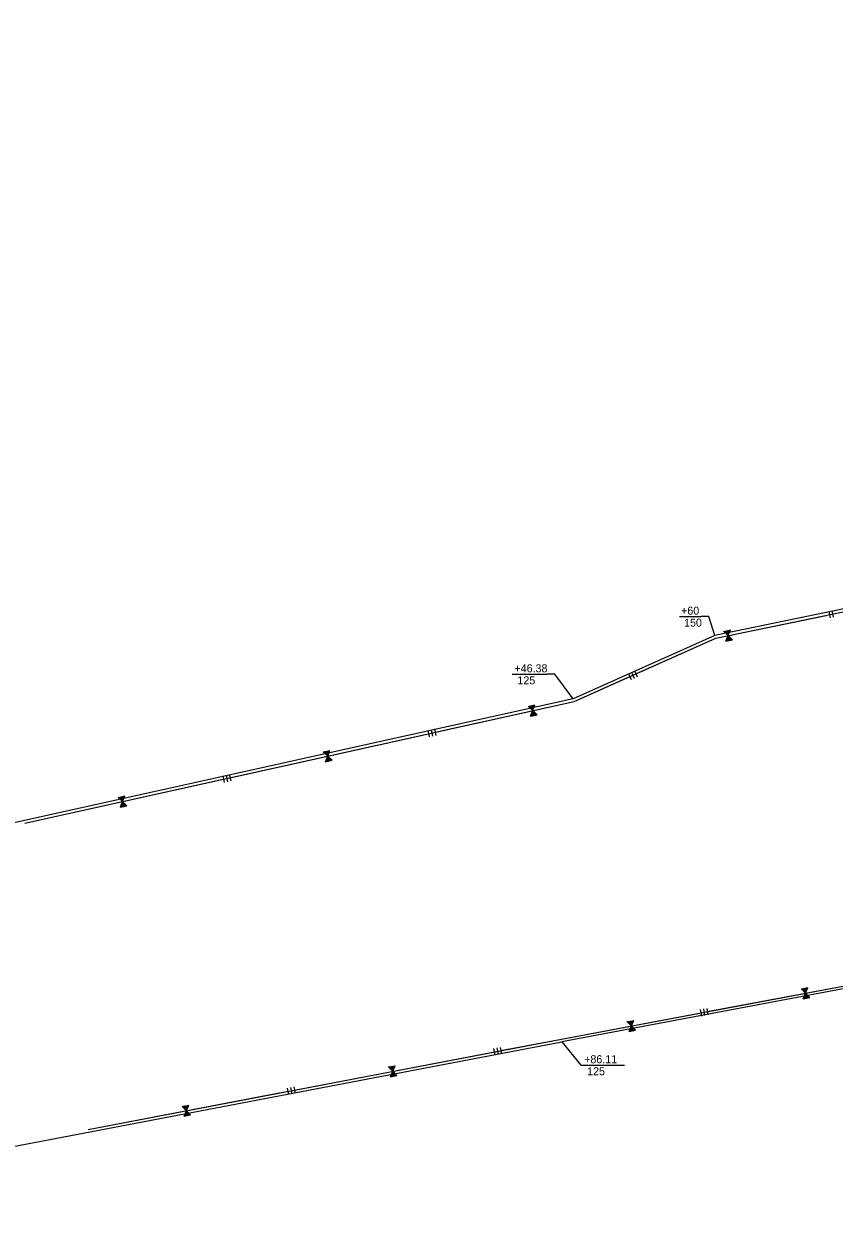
# Model space of a CAD drawing. Extents: x 979729 to 993523, y 1834148 to 1845433.
# Drawn here: x 988823 to 989431, y 1838471 to 1839360 of the extents above; entities that cross this region are included whole.
import ezdxf

# ---------------------------------------------------------------- set-up
doc = ezdxf.new("R2010")
doc.units = 0
for name, color, linetype in [('42', 7, 'Continuous'), ('51', 7, 'Continuous'), ('R_Draft', 7, 'Continuous')]:
    doc.layers.add(name, color=color, linetype=linetype)

msp = doc.modelspace()

# ---------------------------------------------------------------- linework, layer by layer
at = {"layer": '42'}
for p, q in [((989341.75, 1838899.73), (989537.09, 1838940.06)), ((989426.47, 1838919.77), (989427.48, 1838914.88)), ((989428.92, 1838920.28), (989429.93, 1838915.38)), ((989347.87, 1838904.82), (989351.08, 1838901.65)), ((989347.94, 1838904.78), (989347.96, 1838904.84)), ((989348.14, 1838904.61), (989348.26, 1838904.9)), ((989348.32, 1838904.4), (989348.55, 1838904.96)), ((989348.52, 1838904.23), (989348.84, 1838905.02)), ((989348.71, 1838904.02), (989349.14, 1838905.08)), ((989348.89, 1838903.81), (989349.43, 1838905.14)), ((989349.09, 1838903.64), (989349.73, 1838905.21)), ((989349.32, 1838903.53), (989349.96, 1838905.11)), ((989349.49, 1838903.28), (989350.31, 1838905.33)), ((989349.69, 1838903.11), (989350.61, 1838905.39)), ((989349.86, 1838902.88), (989350.9, 1838905.45)), ((989350.08, 1838902.73), (989351.2, 1838905.51)), ((989350.25, 1838902.5), (989351.49, 1838905.57)), ((989350.45, 1838902.33), (989351.79, 1838905.63)), ((989350.63, 1838902.12), (989352.08, 1838905.69)), ((989350.84, 1838901.97), (989352.37, 1838905.75)), ((989351.02, 1838901.74), (989352.67, 1838905.81)), ((989351.08, 1838901.65), (989352.77, 1838905.83)), ((989235.55, 1838852.28), (989341.75, 1838899.73)), ((989349.39, 1838897.48), (989351.08, 1838901.65)), ((989349.43, 1838897.54), (989349.48, 1838897.5)), ((989349.55, 1838897.78), (989349.77, 1838897.56)), ((989349.63, 1838898.04), (989350.07, 1838897.62)), ((989349.75, 1838898.28), (989350.36, 1838897.68)), ((989349.84, 1838898.55), (989350.65, 1838897.74)), ((989349.93, 1838898.81), (989350.95, 1838897.8)), ((989350.04, 1838899.05), (989351.24, 1838897.86)), ((989350.2, 1838899.24), (989351.42, 1838898.04)), ((989350.26, 1838899.53), (989351.83, 1838897.98)), ((989350.38, 1838899.77), (989352.13, 1838898.04)), ((989350.45, 1838900.05), (989352.42, 1838898.1)), ((989350.58, 1838900.27), (989352.71, 1838898.16)), ((989350.65, 1838900.55), (989353.01, 1838898.22)), ((989350.77, 1838900.79), (989353.3, 1838898.29)), ((989350.85, 1838901.05), (989353.6, 1838898.35)), ((989350.99, 1838901.27), (989353.89, 1838898.41)), ((989351.06, 1838901.56), (989354.18, 1838898.47)), ((989351.08, 1838901.65), (989354.28, 1838898.49)), ((989276.38, 1838873.26), (989278.42, 1838868.7)), ((989278.67, 1838874.28), (989280.71, 1838869.72)), ((989280.95, 1838875.3), (989282.99, 1838870.74)), ((988823.9, 1838760.95), (989235.55, 1838852.28)), ((989204.58, 1838845.51), (989206.17, 1838849.6)), ((989204.64, 1838845.42), (989206.27, 1838849.63)), ((989201.39, 1838848.54), (989204.64, 1838845.42)), ((989201.46, 1838848.5), (989201.48, 1838848.56)), ((989201.66, 1838848.33), (989201.77, 1838848.63)), ((989201.85, 1838848.13), (989202.07, 1838848.69)), ((989202.05, 1838847.96), (989202.36, 1838848.76)), ((989202.24, 1838847.75), (989202.65, 1838848.82)), ((989202.43, 1838847.55), (989202.95, 1838848.89)), ((989202.63, 1838847.38), (989203.24, 1838848.95)), ((989202.86, 1838847.27), (989203.47, 1838848.86)), ((989203.01, 1838841.22), (989204.64, 1838845.42)), ((989203.03, 1838847.03), (989203.83, 1838849.08)), ((989203.06, 1838841.29), (989203.1, 1838841.24)), ((989203.17, 1838841.53), (989203.4, 1838841.31)), ((989203.23, 1838846.86), (989204.12, 1838849.15)), ((989203.25, 1838841.79), (989203.69, 1838841.37)), ((989203.37, 1838842.03), (989203.98, 1838841.44)), ((989203.41, 1838846.63), (989204.41, 1838849.21)), ((989203.45, 1838842.3), (989204.28, 1838841.5)), ((989203.53, 1838842.56), (989204.57, 1838841.57)), ((989203.62, 1838846.49), (989204.71, 1838849.28)), ((989203.64, 1838842.8), (989204.86, 1838841.63)), ((989203.8, 1838846.25), (989205, 1838849.34)), ((989203.8, 1838842.99), (989205.04, 1838841.81)), ((989203.86, 1838843.29), (989205.45, 1838841.76)), ((989203.97, 1838843.53), (989205.74, 1838841.83)), ((989204, 1838846.09), (989205.29, 1838849.41)), ((989204.04, 1838843.81), (989206.04, 1838841.89)), ((989204.17, 1838844.03), (989206.33, 1838841.96)), ((989204.19, 1838845.88), (989205.59, 1838849.47)), ((989204.23, 1838844.32), (989206.62, 1838842.02)), ((989204.34, 1838844.55), (989206.92, 1838842.09)), ((989204.41, 1838845.74), (989205.88, 1838849.54)), ((989204.43, 1838844.82), (989207.21, 1838842.15)), ((989204.56, 1838845.04), (989207.5, 1838842.22)), ((989204.62, 1838845.33), (989207.8, 1838842.28)), ((989204.64, 1838845.42), (989207.89, 1838842.3)), ((989126, 1838830.54), (989127.08, 1838825.65)), ((989128.44, 1838831.08), (989129.52, 1838826.2)), ((989130.88, 1838831.62), (989131.96, 1838826.74)), ((989047.63, 1838814.43), (989050.88, 1838811.31)), ((989047.7, 1838814.39), (989047.72, 1838814.45)), ((989047.9, 1838814.22), (989048.01, 1838814.51)), ((989048.09, 1838814.01), (989048.31, 1838814.58)), ((989048.29, 1838813.84), (989048.6, 1838814.64)), ((989048.48, 1838813.64), (989048.89, 1838814.71)), ((989048.67, 1838813.43), (989049.19, 1838814.77)), ((989048.87, 1838813.26), (989049.48, 1838814.84)), ((989049.09, 1838813.16), (989049.71, 1838814.75)), ((989049.27, 1838812.91), (989050.07, 1838814.97)), ((989049.47, 1838812.75), (989050.36, 1838815.03)), ((989049.65, 1838812.51), (989050.65, 1838815.1)), ((989049.86, 1838812.37), (989050.95, 1838815.16)), ((989050.04, 1838812.14), (989051.24, 1838815.23)), ((989050.24, 1838811.97), (989051.53, 1838815.29)), ((989050.43, 1838811.77), (989051.82, 1838815.36)), ((989050.64, 1838811.62), (989052.12, 1838815.42)), ((989050.82, 1838811.39), (989052.41, 1838815.49)), ((989050.88, 1838811.31), (989052.51, 1838815.51)), ((989049.25, 1838807.11), (989050.88, 1838811.31)), ((989049.3, 1838807.17), (989049.34, 1838807.13)), ((989049.41, 1838807.41), (989049.64, 1838807.19)), ((989049.49, 1838807.68), (989049.93, 1838807.26)), ((989049.61, 1838807.91), (989050.22, 1838807.32)), ((989049.69, 1838808.18), (989050.52, 1838807.39)), ((989049.77, 1838808.45), (989050.81, 1838807.45)), ((989049.88, 1838808.69), (989051.1, 1838807.52)), ((989050.04, 1838808.88), (989051.28, 1838807.7)), ((989050.1, 1838809.17), (989051.69, 1838807.65)), ((989050.21, 1838809.41), (989051.98, 1838807.71)), ((989050.28, 1838809.7), (989052.28, 1838807.78)), ((989050.41, 1838809.92), (989052.57, 1838807.84)), ((989050.47, 1838810.2), (989052.86, 1838807.91)), ((989050.58, 1838810.44), (989053.16, 1838807.97)), ((989050.67, 1838810.71), (989053.45, 1838808.04)), ((989050.8, 1838810.92), (989053.74, 1838808.1)), ((989050.86, 1838811.21), (989054.04, 1838808.17)), ((989050.88, 1838811.31), (989054.13, 1838808.19)), ((988972.24, 1838796.42), (988973.32, 1838791.54)), ((988974.68, 1838796.96), (988975.76, 1838792.08)), ((988977.12, 1838797.5), (988978.2, 1838792.62)), ((988893.87, 1838780.31), (988897.12, 1838777.19)), ((988893.93, 1838780.27), (988893.96, 1838780.33)), ((988894.14, 1838780.1), (988894.25, 1838780.4)), ((988894.32, 1838779.9), (988894.54, 1838780.46)), ((988894.53, 1838779.73), (988894.84, 1838780.53)), ((988894.72, 1838779.52), (988895.13, 1838780.59)), ((988894.9, 1838779.32), (988895.42, 1838780.66)), ((988895.11, 1838779.15), (988895.72, 1838780.72)), ((988895.33, 1838779.04), (988895.95, 1838780.63)), ((988895.51, 1838778.8), (988896.3, 1838780.85)), ((988895.71, 1838778.63), (988896.6, 1838780.92)), ((988895.89, 1838778.4), (988896.89, 1838780.98)), ((988896.1, 1838778.26), (988897.19, 1838781.05)), ((988896.28, 1838778.02), (988897.48, 1838781.11)), ((988896.48, 1838777.86), (988897.77, 1838781.18)), ((988896.67, 1838777.65), (988898.06, 1838781.24)), ((988896.88, 1838777.51), (988898.36, 1838781.31)), ((988897.06, 1838777.28), (988898.65, 1838781.37)), ((988897.12, 1838777.19), (988898.75, 1838781.4)), ((988895.49, 1838772.99), (988897.12, 1838777.19)), ((988895.54, 1838773.06), (988895.58, 1838773.01)), ((988895.65, 1838773.3), (988895.88, 1838773.08)), ((988895.73, 1838773.56), (988896.17, 1838773.14)), ((988895.84, 1838773.8), (988896.46, 1838773.21)), ((988895.93, 1838774.07), (988896.76, 1838773.27)), ((988896.01, 1838774.33), (988897.05, 1838773.34)), ((988896.12, 1838774.57), (988897.34, 1838773.4)), ((988896.28, 1838774.76), (988897.52, 1838773.58)), ((988896.34, 1838775.06), (988897.93, 1838773.53)), ((988896.45, 1838775.3), (988898.22, 1838773.6)), ((988896.51, 1838775.58), (988898.52, 1838773.66)), ((988896.65, 1838775.8), (988898.81, 1838773.73)), ((988896.71, 1838776.09), (988899.1, 1838773.79)), ((988896.82, 1838776.32), (988899.4, 1838773.86)), ((988896.91, 1838776.59), (988899.69, 1838773.92)), ((988897.04, 1838776.81), (988899.98, 1838773.99)), ((988897.1, 1838777.1), (988900.28, 1838774.05)), ((988897.12, 1838777.19), (988900.37, 1838774.07)), ((989226.06, 1838599.13), (989775.94, 1838702.44)), ((989406.03, 1838636.76), (989409.18, 1838633.53)), ((989406.09, 1838636.72), (989406.12, 1838636.78)), ((989406.29, 1838636.54), (989406.42, 1838636.83)), ((989406.47, 1838636.33), (989406.71, 1838636.89)), ((989406.67, 1838636.15), (989407.01, 1838636.94)), ((989406.85, 1838635.94), (989407.3, 1838637)), ((989407.03, 1838635.73), (989407.6, 1838637.05)), ((989407.23, 1838635.55), (989407.89, 1838637.11)), ((989407.45, 1838635.44), (989408.12, 1838637.01)), ((989407.62, 1838635.19), (989408.48, 1838637.22)), ((989407.82, 1838635.02), (989408.78, 1838637.27)), ((989407.99, 1838634.78), (989409.07, 1838637.33)), ((989408.2, 1838634.63), (989409.37, 1838637.39)), ((989408.37, 1838634.39), (989409.66, 1838637.44)), ((989408.56, 1838634.22), (989409.96, 1838637.5)), ((989408.74, 1838634.01), (989410.25, 1838637.55)), ((989408.95, 1838633.86), (989410.55, 1838637.61)), ((989409.12, 1838633.62), (989410.84, 1838637.66)), ((989409.18, 1838633.53), (989410.94, 1838637.68)), ((989407.41, 1838629.39), (989409.18, 1838633.53)), ((989407.46, 1838629.45), (989407.5, 1838629.4)), ((989407.58, 1838629.69), (989407.8, 1838629.46)), ((989407.67, 1838629.95), (989408.1, 1838629.52)), ((989407.79, 1838630.18), (989408.39, 1838629.57)), ((989407.88, 1838630.45), (989408.69, 1838629.63)), ((989407.98, 1838630.71), (989408.98, 1838629.68)), ((989408.1, 1838630.95), (989409.28, 1838629.74)), ((989408.26, 1838631.13), (989409.46, 1838629.91)), ((989408.33, 1838631.42), (989409.87, 1838629.85)), ((989408.45, 1838631.66), (989410.16, 1838629.9)), ((989408.52, 1838631.94), (989410.46, 1838629.96)), ((989408.66, 1838632.16), (989410.75, 1838630.01)), ((989408.73, 1838632.44), (989411.05, 1838630.07)), ((989408.85, 1838632.67), (989411.34, 1838630.13)), ((989408.94, 1838632.94), (989411.64, 1838630.18)), ((989409.08, 1838633.15), (989411.93, 1838630.24)), ((989409.16, 1838633.44), (989412.23, 1838630.29)), ((989409.18, 1838633.53), (989412.33, 1838630.31)), ((989330.09, 1838621.22), (989331.02, 1838616.31)), ((989332.55, 1838621.68), (989333.47, 1838616.77)), ((989335.01, 1838622.14), (989335.93, 1838617.23)), ((989275.42, 1838612.16), (989278.57, 1838608.94)), ((989275.48, 1838612.12), (989275.51, 1838612.18)), ((989275.68, 1838611.94), (989275.8, 1838612.23)), ((989275.86, 1838611.73), (989276.1, 1838612.29)), ((989276.06, 1838611.55), (989276.4, 1838612.34)), ((989276.24, 1838611.34), (989276.69, 1838612.4)), ((989276.42, 1838611.13), (989276.99, 1838612.45)), ((989276.62, 1838610.96), (989277.28, 1838612.51)), ((989276.84, 1838610.84), (989277.51, 1838612.41)), ((989277.01, 1838610.59), (989277.87, 1838612.62)), ((989277.21, 1838610.42), (989278.17, 1838612.68)), ((989277.38, 1838610.18), (989278.46, 1838612.73)), ((989277.59, 1838610.03), (989278.76, 1838612.79)), ((989277.76, 1838609.79), (989279.05, 1838612.84)), ((989277.95, 1838609.62), (989279.35, 1838612.9)), ((989278.13, 1838609.41), (989279.64, 1838612.95)), ((989278.34, 1838609.26), (989279.94, 1838613.01)), ((989278.51, 1838609.02), (989280.23, 1838613.06)), ((989278.57, 1838608.94), (989280.33, 1838613.08)), ((989276.8, 1838604.79), (989278.57, 1838608.94)), ((989276.85, 1838604.85), (989276.89, 1838604.81)), ((989276.97, 1838605.09), (989277.19, 1838604.86)), ((989277.06, 1838605.35), (989277.48, 1838604.92)), ((989277.18, 1838605.58), (989277.78, 1838604.97)), ((989277.27, 1838605.85), (989278.07, 1838605.03)), ((989277.37, 1838606.11), (989278.37, 1838605.08)), ((989277.49, 1838606.35), (989278.67, 1838605.14)), ((989277.65, 1838606.53), (989278.84, 1838605.31)), ((989277.72, 1838606.83), (989279.26, 1838605.25)), ((989277.84, 1838607.06), (989279.55, 1838605.3)), ((989277.91, 1838607.34), (989279.85, 1838605.36)), ((989278.05, 1838607.56), (989280.14, 1838605.42)), ((989278.12, 1838607.84), (989280.44, 1838605.47)), ((989278.24, 1838608.08), (989280.73, 1838605.53)), ((989278.33, 1838608.34), (989281.03, 1838605.58)), ((989278.47, 1838608.55), (989281.32, 1838605.64)), ((989278.55, 1838608.84), (989281.62, 1838605.69)), ((989278.57, 1838608.94), (989281.72, 1838605.71)), ((988871.3, 1838531.37), (989226.06, 1838599.13)), ((989175.32, 1838591.98), (989176.26, 1838587.07)), ((989177.78, 1838592.45), (989178.72, 1838587.54)), ((989180.23, 1838592.92), (989181.17, 1838588.01)), ((989096.51, 1838578.2), (989099.67, 1838574.99)), ((989096.57, 1838578.16), (989096.6, 1838578.22)), ((989096.77, 1838577.99), (989096.89, 1838578.28)), ((989096.95, 1838577.77), (989097.19, 1838578.33)), ((989097.15, 1838577.6), (989097.48, 1838578.39)), ((989097.33, 1838577.39), (989097.78, 1838578.45)), ((989097.52, 1838577.18), (989098.08, 1838578.5)), ((989097.71, 1838577), (989098.37, 1838578.56)), ((989097.91, 1838570.84), (989099.67, 1838574.99)), ((989097.94, 1838576.89), (989098.6, 1838578.46)), ((989098.1, 1838576.64), (989098.96, 1838578.67)), ((989098.3, 1838576.47), (989099.26, 1838578.73)), ((989098.47, 1838576.23), (989099.55, 1838578.78)), ((989098.68, 1838576.08), (989099.85, 1838578.84)), ((989098.85, 1838575.84), (989100.14, 1838578.9)), ((989099.05, 1838575.67), (989100.44, 1838578.95)), ((989099.23, 1838575.46), (989100.73, 1838579.01)), ((989099.23, 1838573.89), (989101.55, 1838571.53)), ((989099.34, 1838574.13), (989101.84, 1838571.59)), ((989099.44, 1838575.31), (989101.03, 1838579.07)), ((989099.44, 1838574.39), (989102.14, 1838571.64)), ((989099.57, 1838574.61), (989102.43, 1838571.7)), ((989099.61, 1838575.07), (989101.32, 1838579.12)), ((989099.65, 1838574.89), (989102.73, 1838571.76)), ((989099.67, 1838574.99), (989101.42, 1838579.14)), ((989099.67, 1838574.99), (989102.83, 1838571.77)), ((989097.96, 1838570.9), (989098.01, 1838570.85)), ((989098.08, 1838571.14), (989098.3, 1838570.91)), ((989098.17, 1838571.4), (989098.6, 1838570.97)), ((989098.29, 1838571.63), (989098.89, 1838571.02)), ((989098.38, 1838571.9), (989099.19, 1838571.08)), ((989098.47, 1838572.16), (989099.48, 1838571.14)), ((989098.59, 1838572.4), (989099.78, 1838571.19)), ((989098.76, 1838572.59), (989099.96, 1838571.37)), ((989098.82, 1838572.88), (989100.37, 1838571.3)), ((989098.94, 1838573.11), (989100.66, 1838571.36)), ((989099.01, 1838573.39), (989100.96, 1838571.42)), ((989099.15, 1838573.61), (989101.25, 1838571.47)), ((989020.62, 1838562.43), (989021.56, 1838557.52)), ((989023.07, 1838562.9), (989024.01, 1838557.99)), ((989025.53, 1838563.37), (989026.47, 1838558.46)), ((988941.8, 1838548.65), (988944.96, 1838545.44)), ((988941.87, 1838548.61), (988941.9, 1838548.67)), ((988942.07, 1838548.44), (988942.19, 1838548.73)), ((988942.25, 1838548.22), (988942.49, 1838548.78)), ((988942.45, 1838548.05), (988942.78, 1838548.84)), ((988942.63, 1838547.84), (988943.08, 1838548.9)), ((988942.81, 1838547.63), (988943.37, 1838548.95)), ((988943.01, 1838547.45), (988943.67, 1838549.01)), ((988943.23, 1838547.34), (988943.9, 1838548.91)), ((988943.4, 1838547.09), (988944.26, 1838549.12)), ((988943.6, 1838546.92), (988944.55, 1838549.18)), ((988943.77, 1838546.68), (988944.85, 1838549.23)), ((988943.98, 1838546.53), (988945.14, 1838549.29)), ((988944.15, 1838546.29), (988945.44, 1838549.35)), ((988944.35, 1838546.12), (988945.73, 1838549.4)), ((988944.53, 1838545.91), (988946.03, 1838549.46)), ((988944.74, 1838545.76), (988946.32, 1838549.52)), ((988944.91, 1838545.52), (988946.62, 1838549.57)), ((988944.96, 1838545.44), (988946.72, 1838549.59)), ((988943.21, 1838541.29), (988944.96, 1838545.44)), ((988943.26, 1838541.35), (988943.3, 1838541.3)), ((988943.38, 1838541.59), (988943.6, 1838541.36)), ((988943.47, 1838541.85), (988943.89, 1838541.42)), ((988943.59, 1838542.08), (988944.19, 1838541.47)), ((988943.68, 1838542.35), (988944.48, 1838541.53)), ((988943.77, 1838542.61), (988944.78, 1838541.59)), ((988943.89, 1838542.85), (988945.07, 1838541.64)), ((988944.05, 1838543.04), (988945.25, 1838541.82)), ((988944.12, 1838543.33), (988945.66, 1838541.75)), ((988944.24, 1838543.56), (988945.96, 1838541.81)), ((988944.31, 1838543.84), (988946.25, 1838541.87)), ((988944.45, 1838544.06), (988946.55, 1838541.92)), ((988944.52, 1838544.34), (988946.84, 1838541.98)), ((988944.64, 1838544.58), (988947.14, 1838542.04)), ((988944.73, 1838544.84), (988947.43, 1838542.09)), ((988944.87, 1838545.06), (988947.73, 1838542.15)), ((988944.94, 1838545.34), (988948.02, 1838542.21)), ((988944.96, 1838545.44), (988948.12, 1838542.22))]:
    msp.add_line(p, q, dxfattribs=at)
for points in [[(989281.97, 1838873.02), (989341.75, 1838899.73), (989424.53, 1838916.82)], [(989347.87, 1838904.82), (989352.77, 1838905.83)], [(989349.39, 1838897.48), (989354.28, 1838898.49)], [(989131.42, 1838829.18), (989235.55, 1838852.28), (989275.12, 1838869.96)], [(989201.39, 1838848.54), (989206.27, 1838849.63)], [(989203.01, 1838841.22), (989207.89, 1838842.3)], [(988977.66, 1838795.06), (989124.1, 1838827.55)], [(989047.63, 1838814.43), (989052.51, 1838815.51)], [(989049.25, 1838807.11), (989054.13, 1838808.19)], [(988823.9, 1838760.95), (988970.34, 1838793.44)], [(988893.87, 1838780.31), (988898.75, 1838781.4)], [(988895.49, 1838772.99), (988900.37, 1838774.07)], [(989335.47, 1838619.69), (989482.89, 1838647.38)], [(989406.03, 1838636.76), (989410.94, 1838637.68)], [(989407.41, 1838629.39), (989412.33, 1838630.31)], [(989226.06, 1838599.13), (989328.1, 1838618.3)], [(989275.42, 1838612.16), (989280.33, 1838613.08)], [(989276.8, 1838604.79), (989281.72, 1838605.71)], [(989180.7, 1838590.47), (989226.06, 1838599.13)], [(989026, 1838560.92), (989173.33, 1838589.06)], [(989096.51, 1838578.2), (989101.42, 1838579.14)], [(989097.91, 1838570.84), (989102.83, 1838571.77)], [(988871.3, 1838531.37), (989018.63, 1838559.51)], [(988941.8, 1838548.65), (988946.72, 1838549.59)], [(988943.21, 1838541.29), (988948.12, 1838542.22)]]:
    msp.add_lwpolyline(points, dxfattribs=at)
at = {"layer": '51'}
for p, q in [((989234.92, 1838854.19), (988573.1, 1838707.35)), ((989776.33, 1838700.48), (989226.43, 1838597.17)), ((988564.68, 1838470.76), (989226.43, 1838597.17))]:
    msp.add_line(p, q, dxfattribs=at)
msp.add_lwpolyline([(990790.39, 1839360.39), (990495.54, 1839185.59), (990219.53, 1839055.3), (989873.17, 1838970.64), (989662.61, 1838927.17), (989537.01, 1838942.08), (989341.14, 1838901.64), (989234.92, 1838854.19)], dxfattribs=at)
at = {"layer": 'R_Draft'}
for p, q in [((989314.74, 1838915.84), (989330.54, 1838915.84)), ((989189.11, 1838872.59), (989215.15, 1838872.59)), ((989246.76, 1838579.51), (989273.35, 1838579.51))]:
    msp.add_line(p, q, dxfattribs=at)
for points in [[(989341.14, 1838901.64), (989336.54, 1838915.84), (989330.54, 1838915.84)], [(989234.92, 1838854.19), (989221.15, 1838872.59), (989215.15, 1838872.59)], [(989226.43, 1838597.17), (989240.76, 1838579.51), (989246.76, 1838579.51)]]:
    msp.add_lwpolyline(points, dxfattribs=at)

# ---------------------------------------------------------------- texts
for s, p in [('+60', (989315.82, 1838917.34)), (' 150', (989315.82, 1838908.34)), ('+46.38', (989190.88, 1838874.09)), (' 125', (989190.88, 1838865.09)), ('+86.11', (989243.14, 1838581.01)), (' 125', (989243.14, 1838572.01))]:
    msp.add_text(s, height=6, rotation=360, dxfattribs=at).set_placement(p)

doc.saveas('drawing.dxf')
